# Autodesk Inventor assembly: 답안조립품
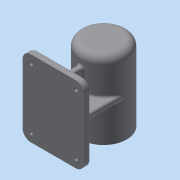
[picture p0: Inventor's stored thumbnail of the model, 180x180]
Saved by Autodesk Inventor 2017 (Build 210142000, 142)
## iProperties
Part Number: 답안조립품
Material: 일반
Document SubType Name: Assembly
Designer: mrc
Author: mrc
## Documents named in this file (2)
- C:\Users\mrc\Desktop\701004V1031\답안조립품.iam
- C:\Users\mrc\Desktop\701004V1031\본체.ipt
